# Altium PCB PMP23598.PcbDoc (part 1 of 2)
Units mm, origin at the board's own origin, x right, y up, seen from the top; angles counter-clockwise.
Board outline 80 x 60 mm, 4 copper layers (Top Layer, Layer 1, Layer 2, Bottom Layer), stack 1.856 mm thick; 92 components, 46 nets, 417 pads, 121 vias.
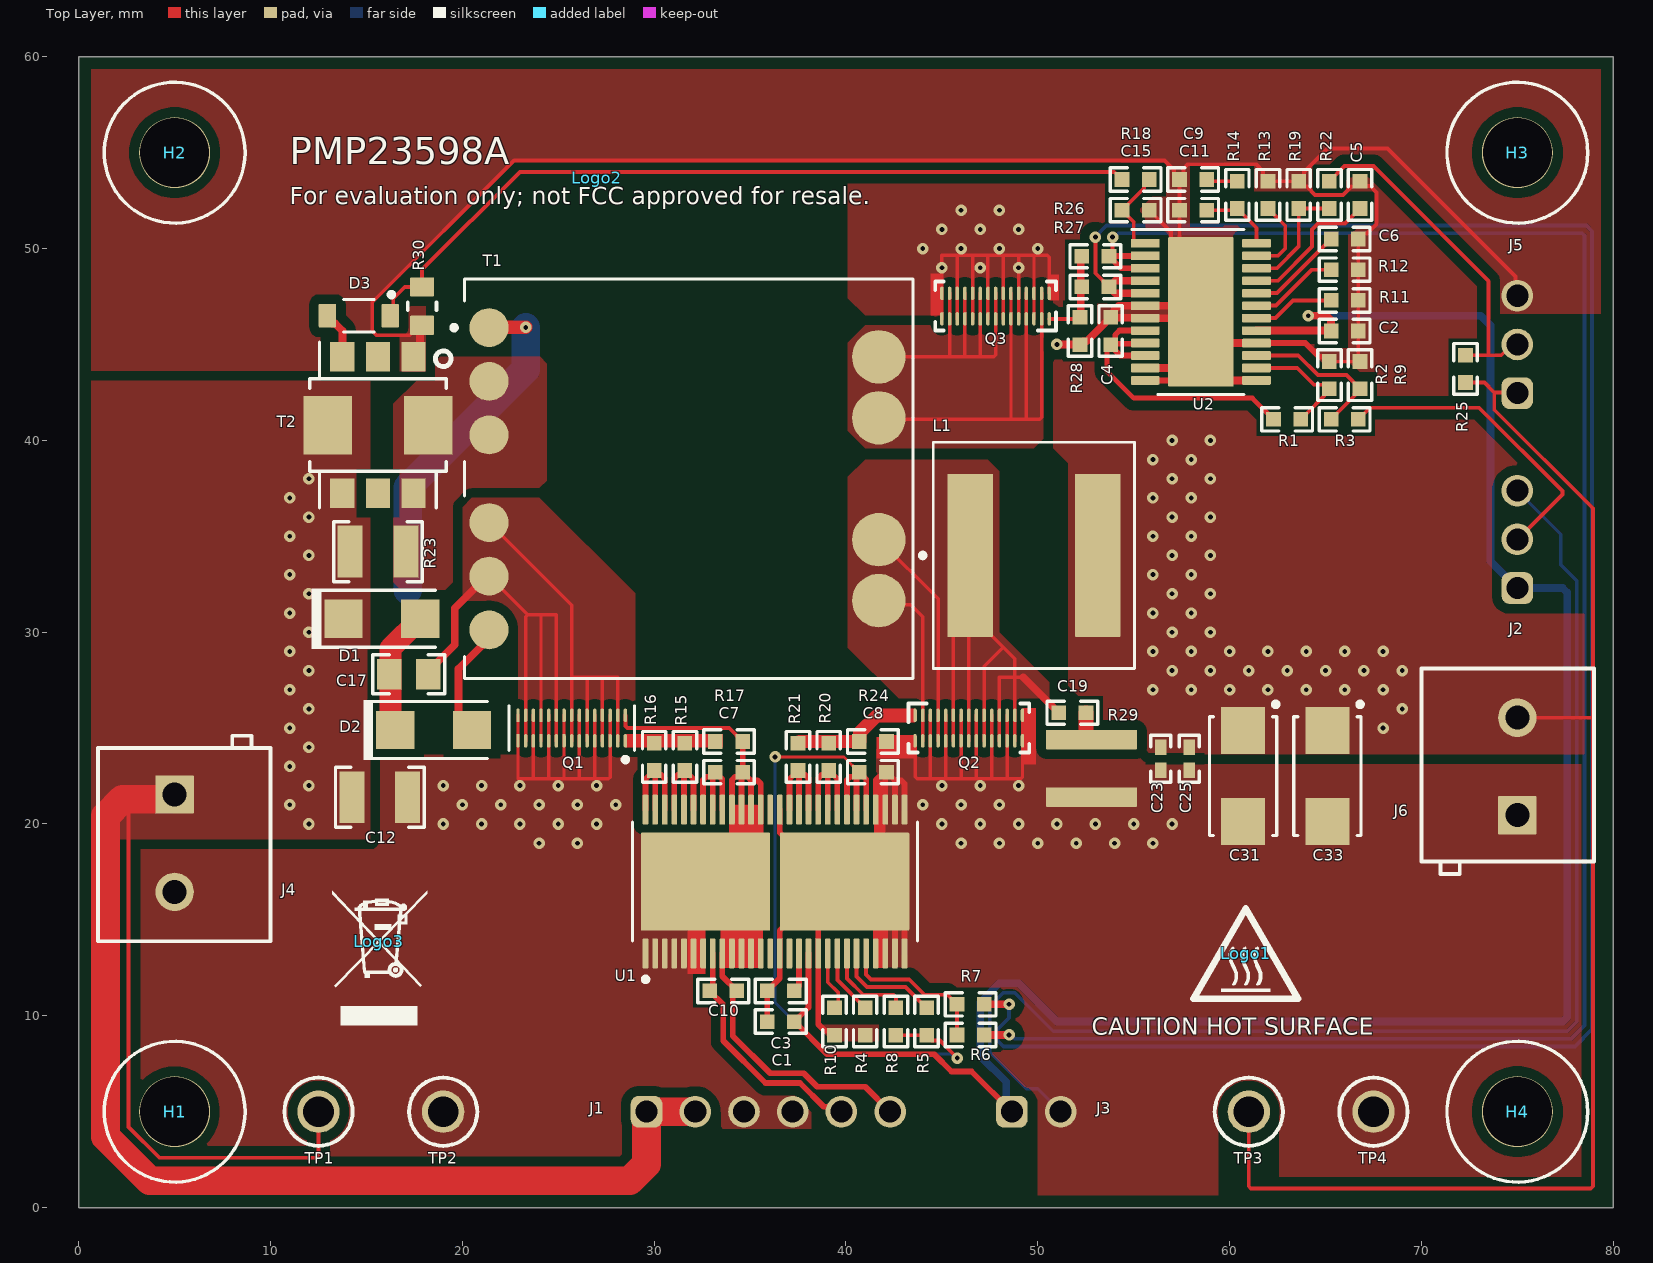
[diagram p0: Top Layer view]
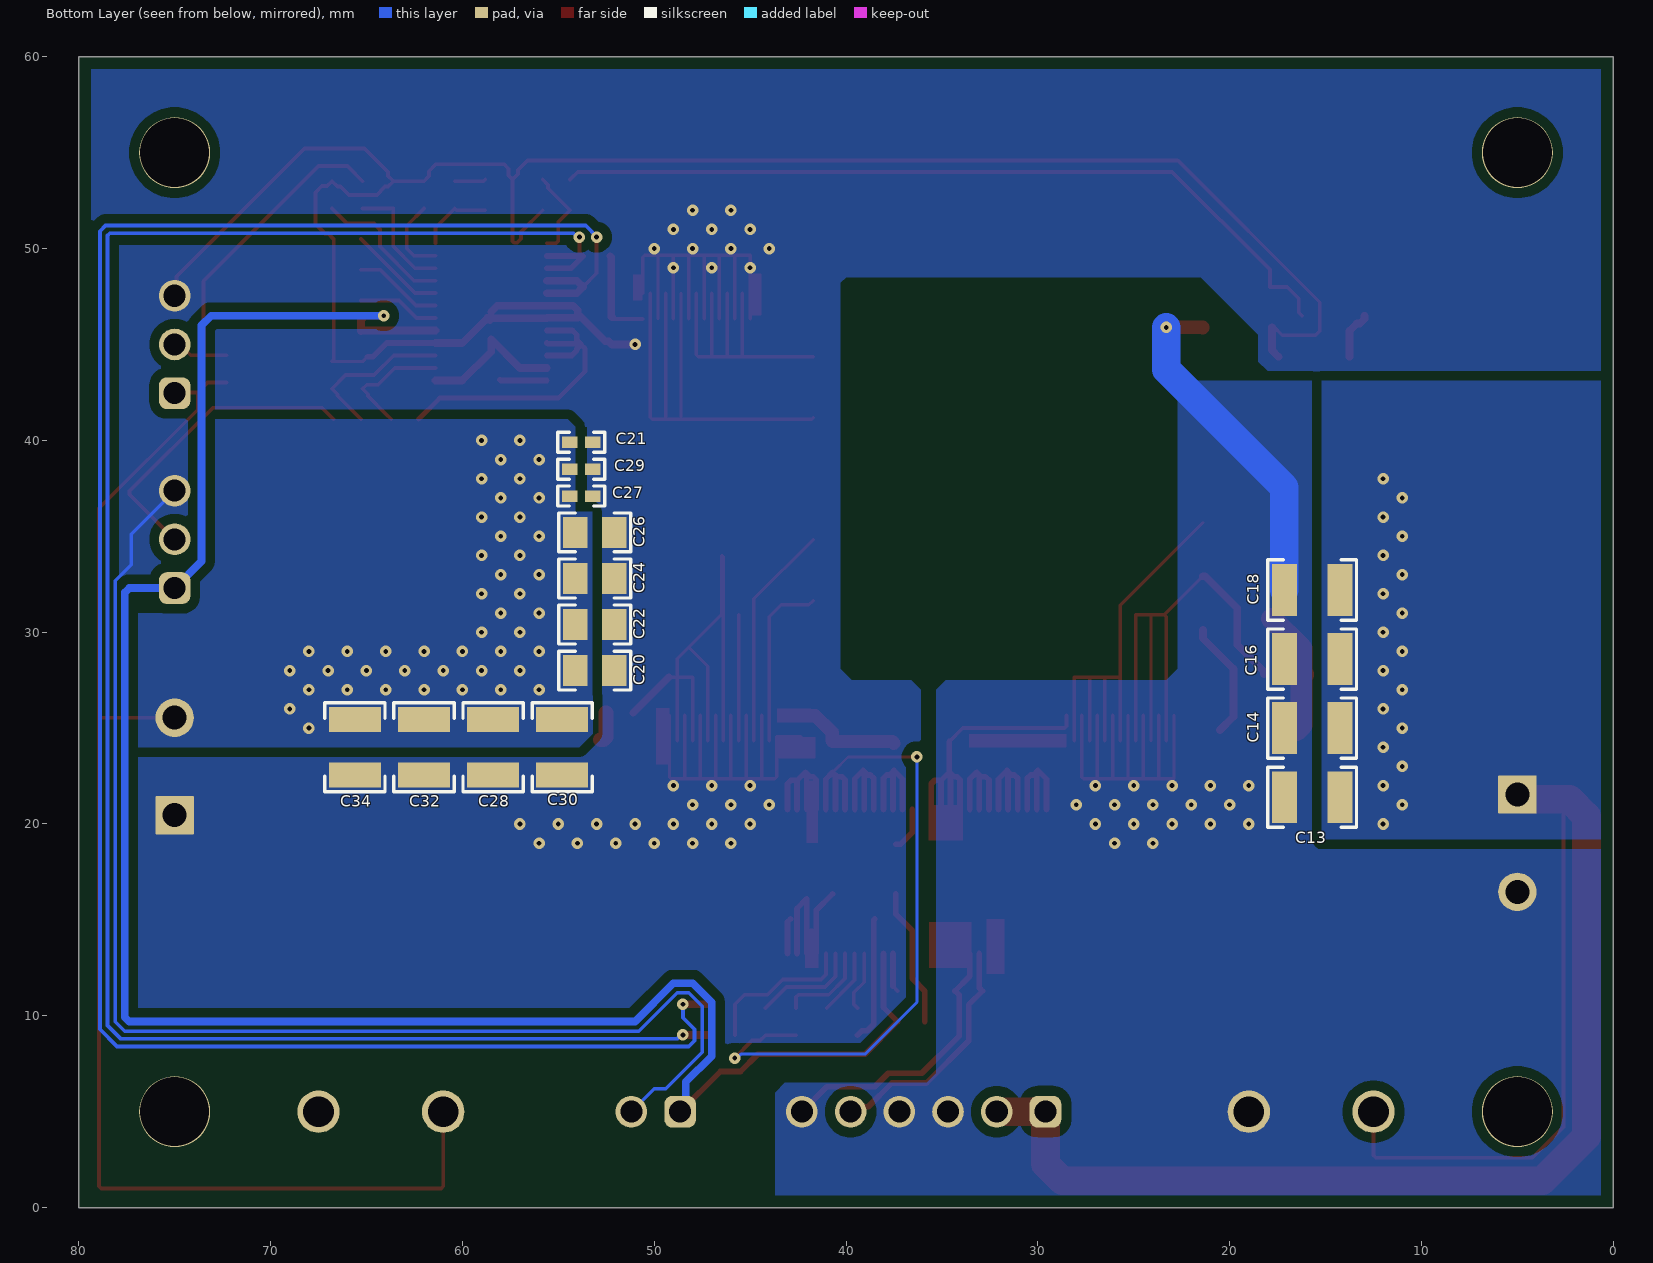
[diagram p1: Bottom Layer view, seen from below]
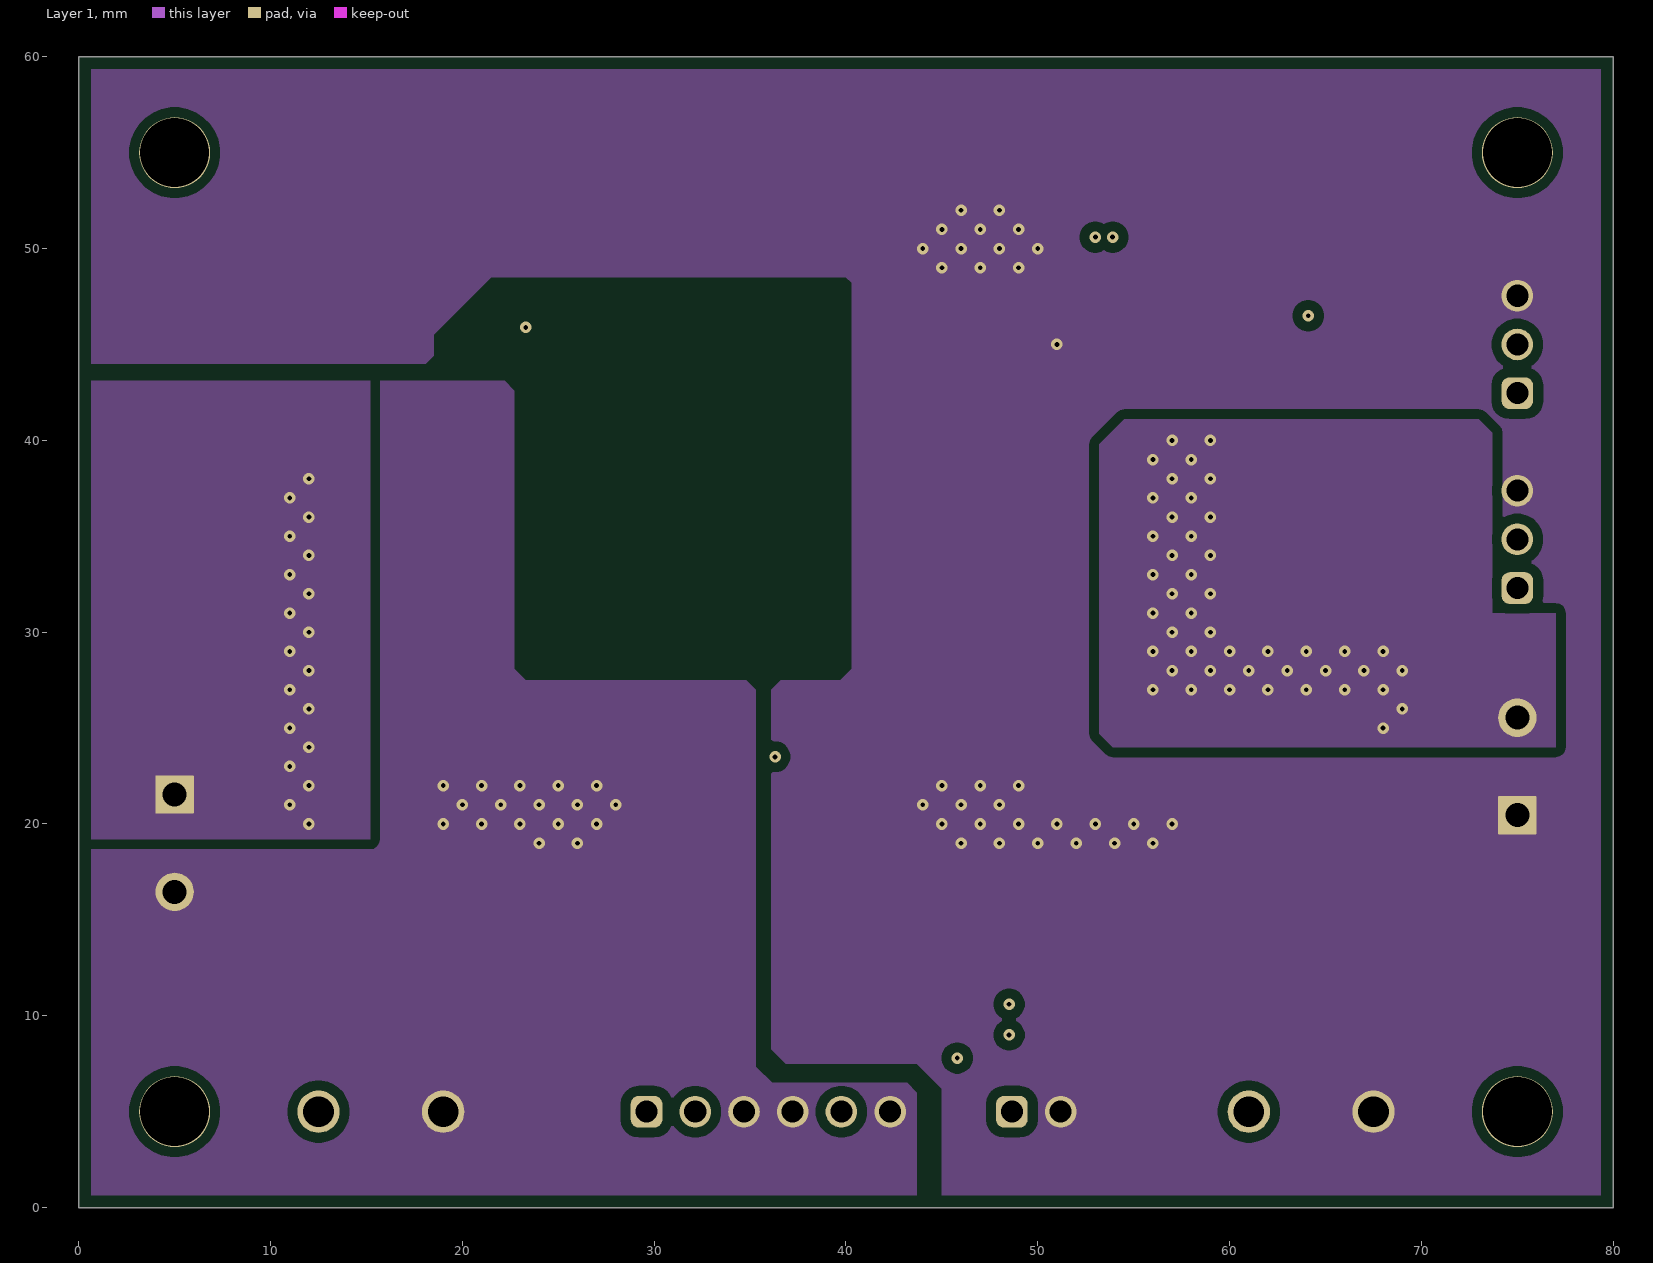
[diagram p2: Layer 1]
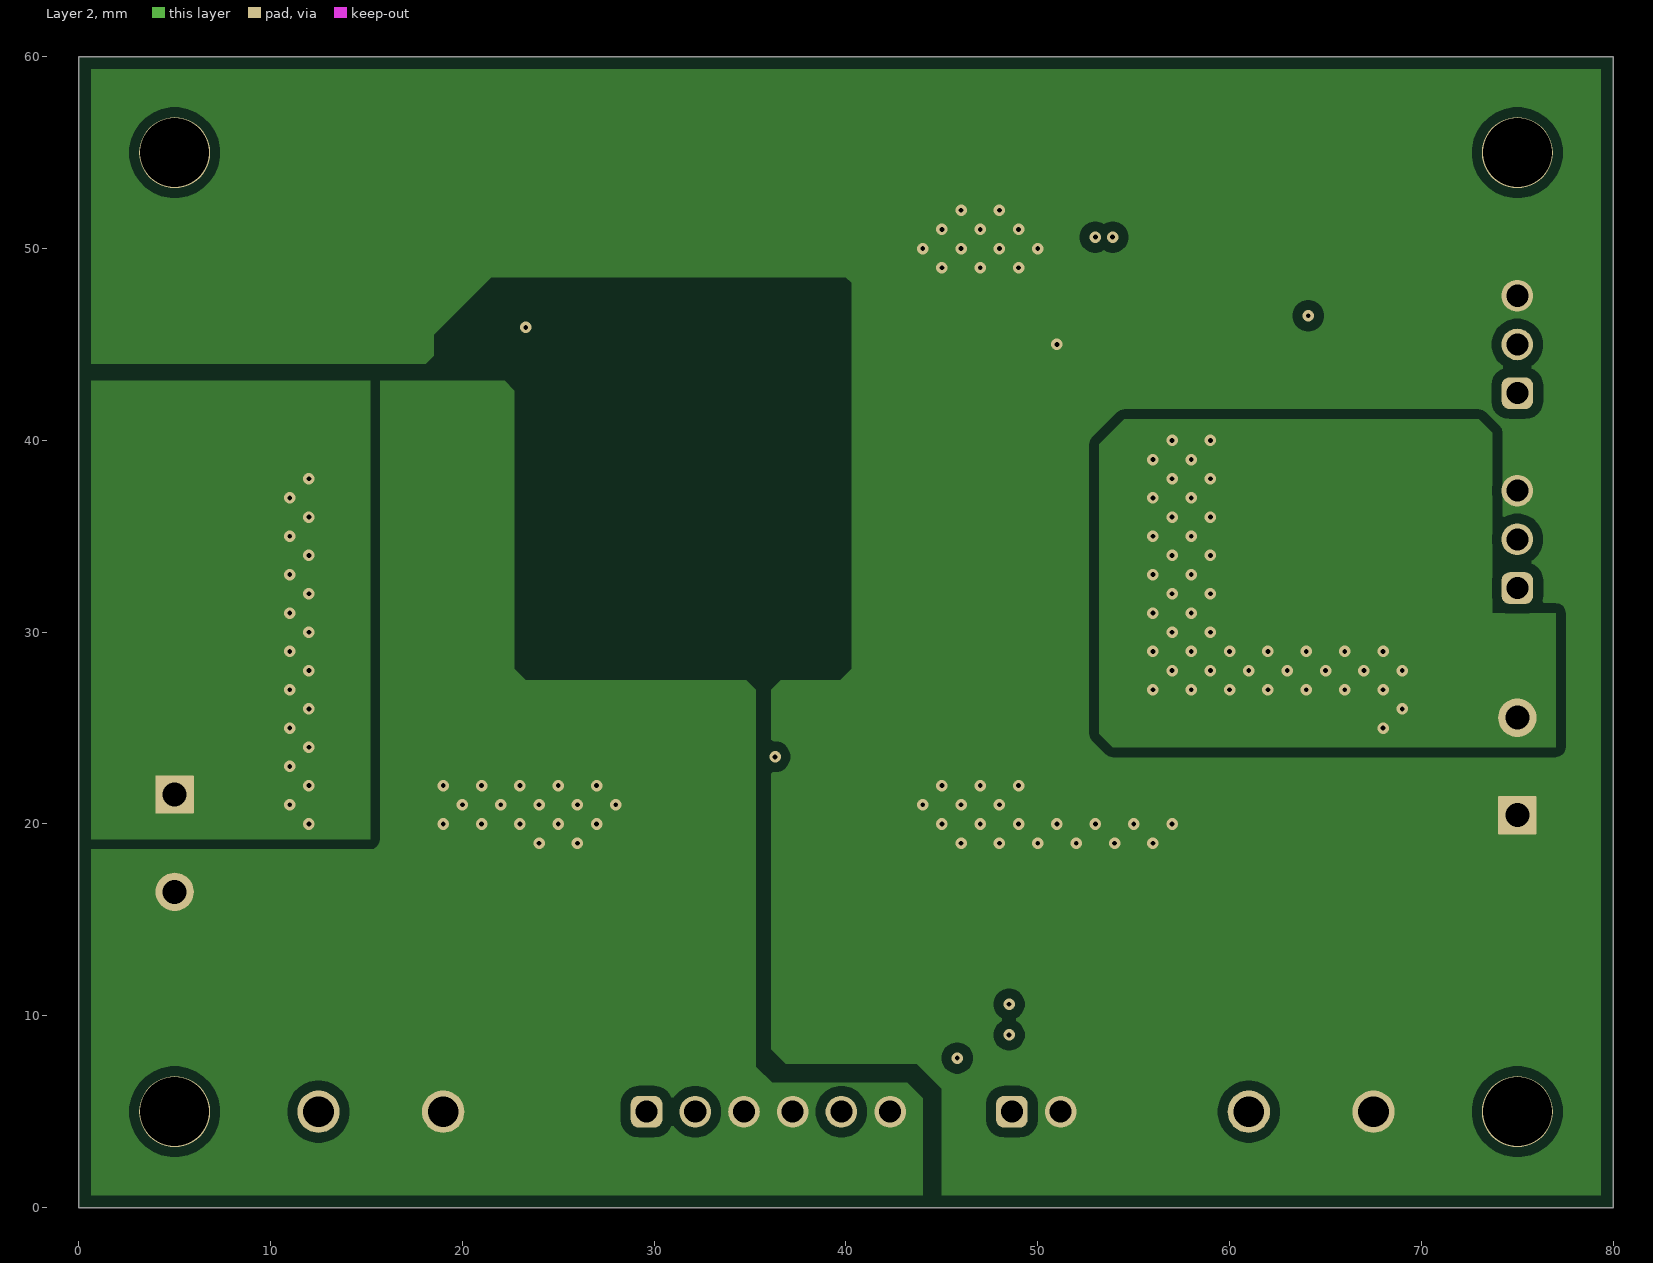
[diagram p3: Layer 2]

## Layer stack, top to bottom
Top Solder: solder mask 0.0102, Solder Resist, Dk 3.5
Top Layer: signal copper 0.07
Dielectric 1: prepreg 0.0711, PP-006, Dk 4.1
Layer 1: signal copper 0.035
Dielectric1: core 1.5037, FR-4 High Tg, Dk 4.8
Layer 2: signal copper 0.035
Dielectric 2: prepreg 0.0711, PP-006, Dk 4.1
Bottom Layer: signal copper 0.07
Bottom Solder: solder mask 0.0102, Solder Resist, Dk 3.5

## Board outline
0,0 0,60 80,60 80,0

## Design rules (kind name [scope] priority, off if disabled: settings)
AcuteAngle [All] p1: minimum=4.50000000000000E+0001 checktracksonly=FALSE
AssemblyTestPointUsage [All] p1: valid=2
BoardOutlineClearance BoardOutlineClearance_MountingHoles [OnCopper and InComponentClass('Mounting Holes')] p1: gap=0.635 ignorepadtopadclearanceinfootprint=FALSE
BoardOutlineClearance BoardOutlineClearance_Poly [OnCopper and InPoly] p2: gap=0.635 ignorepadtopadclearanceinfootprint=FALSE
BoardOutlineClearance [OnCopper and Not InComponentClass('Logo') and not InComponentClass('FiducialMark') and not InRegion(1000,500,4000,800)] p3: gap=0.635 ignorepadtopadclearanceinfootprint=FALSE
Clearance Clearance_2 [InNetClass('HV') vs Not InNetClass('HV')] p1: gap=1.524 ignorepadtopadclearanceinfootprint=FALSE
Clearance Clearance_1 [InNetClass('MV') vs Not InNetClass('MV')] p2: gap=0.762 ignorepadtopadclearanceinfootprint=FALSE
Clearance Clearance_Keepouts [((IsTrack Or IsArc) And Not InPoly) And IsFree and IsKeepOut vs ((IsTrack Or IsArc) And Not InPoly) And IsFree and IsKeepOut] p3: gap=0 ignorepadtopadclearanceinfootprint=FALSE
Clearance Clearance_BoardEdge_MountingHoles [OnCopper and InComponentClass('Mounting Holes') vs IsKeepOut] p4: gap=1.016 ignorepadtopadclearanceinfootprint=FALSE except(0: Arc-Hole Track-Hole SMDPad-Hole THPad-Hole Via-Hole Fill-Hole Poly-Hole Region-Hole Text-Hole)
Clearance Clearance_BoardEdge_Poly [OnCopper and InPoly vs IsKeepOut] p5: gap=1.27 ignorepadtopadclearanceinfootprint=FALSE except(0: Arc-Hole Track-Hole SMDPad-Hole THPad-Hole Via-Hole Fill-Hole Poly-Hole Region-Hole Text-Hole)
Clearance Clearance_BoardEdge [OnCopper and Not InComponentClass('Logo') and not InComponentClass('FiducialMark') and not InRegion(1000,500,4000,800) and Not IsKeepout vs IsKeepOut] p6: gap=1.27 ignorepadtopadclearanceinfootprint=FALSE
Clearance Clearance_Poly [InPolygon] p7: gap=0.508 ignorepadtopadclearanceinfootprint=FALSE except(0: Arc-Hole Track-Hole SMDPad-Hole THPad-Hole Via-Hole Fill-Hole Poly-Hole Region-Hole Text-Hole)
Clearance [All] p8: gap=0.152 ignorepadtopadclearanceinfootprint=FALSE
ComponentClearance ComponentClearance_MountingHoles_FiducialMarks [InComponentClass('Mounting Holes') vs InComponentClass('FiducialMark')] p1: gap=0.508 collisioncheckmode=3 verticalgap=0.254 showdistances=FALSE
ComponentClearance ComponentClearance_Shunt [InComponentClass('Header') vs InComponentClass('Shunt')] p2: gap=0 collisioncheckmode=3 verticalgap=0 showdistances=FALSE
ComponentClearance ComponentClearance_Logo [InComponentClass('Logo')] p3: gap=0.127 collisioncheckmode=3 verticalgap=0.254 showdistances=FALSE
ComponentClearance ComponentClearance_ScrewToNut [(HasFootprint('NY PMS 440 0025 PH')) vs (HasFootprint('Keystone_1902C'))] p4: gap=0.508 collisioncheckmode=3 verticalgap=2540 showdistances=FALSE
ComponentClearance ComponentClearance_MountingHoles [InComponentClass('Mounting Holes')] p5: gap=0.508 collisioncheckmode=3 verticalgap=0.254 showdistances=FALSE
ComponentClearance ComponentClearance_SmallPassives [HasFootprint('0201*') or HasFootprint('0402*') or HasFootprint('0508') or HasFootprint('0603*') or HasFootprint('0612') or HasFootprint('0805*') or HasFootprint('0815*') or HasFootprint('0830*') or HasFootprint('1206*') or HasFootprint('1210*') or HasFootprint('1808*') or HasFootprint('1812*') or HasFootprint('1825*') or HasFootprint('2010*') or HasFootprint('2220*') or HasFootprint('2225*') or HasFootprint('2512*') or HasFootprint('2728*') or HasFootprint('3518*') vs HasFootprint('0201*') or HasFootprint('0402*') or HasFootprint('0508') or HasFootprint('0603*') or HasFootprint('0612') or HasFootprint('0805*') or HasFootprint('0815*') or HasFootprint('0830*') or HasFootprint('1206*') or HasFootprint('1210*') or HasFootprint('1808*') or HasFootprint('1812*') or HasFootprint('1825*') or HasFootprint('2010*') or HasFootprint('2220*') or HasFootprint('2225*') or HasFootprint('2512*') or HasFootprint('2728*') or HasFootprint('3518*')] p6: gap=0.508 collisioncheckmode=3 verticalgap=0.508 showdistances=FALSE
ComponentClearance ComponentClearance_THtoSMT [IsThruComponent vs IsSMTComponent] p7: gap=0.254 collisioncheckmode=3 verticalgap=0.254 showdistances=FALSE
ComponentClearance ComponentClearance_THtoTH [IsThruComponent vs IsThruComponent] p8: gap=0.254 collisioncheckmode=3 verticalgap=0.254 showdistances=FALSE
ComponentClearance [All] p9: gap=0.254 collisioncheckmode=3 verticalgap=0.254 showdistances=FALSE
DiffPairsRouting [All] p1: maxlimit=2.54 minlimit=0.254 mostfreqgap=0.254 toplayer_minwidth=0.381 toplayer_maxwidth=0.381 toplayer_prefwidth=0.381 midlayer1_minwidth=0.381 midlayer1_maxwidth=0.381 midlayer1_prefwidth=0.381 midlayer2_minwidth=0.381 midlayer2_maxwidth=0.381 midlayer2_prefwidth=0.381 bottomlayer_minwidth=0.381 bottomlayer_maxwidth=0.381 bottomlayer_prefwidth=0.381 maxuncoupledlength=25.4
FabricationTestPointUsage TestPointUsage [All] p1: valid=2 allowmultiple=FALSE
FabricationTestpoint Testpoint [All] p1: side=3 testpointundercomponent=TRUE minsize=1.016 maxsize=2.54 preferedsize=1.524 minholesize=0 maxholesize=1.016 preferedholesize=0.813 testpointgrid=0.025 allowsidetop=TRUE allowsidebottom=TRUE usegrid=TRUE gridtolerance=0
FanoutControl Fanout_LCC [IsLCC] p1: bgadir=Out bgaviamode=Centered fanoutstyle=Auto fanoutdirection=Alternating viagrid=0.025 // Fanout_LCC (Default Rule)
FanoutControl Fanout_BGA [IsBGA] p2: bgadir=Out bgaviamode=Centered fanoutstyle=Auto fanoutdirection=Alternating viagrid=0.025 // Fanout_BGA (Default Rule)
FanoutControl Fanout_Default [All] p4: bgadir=Out bgaviamode=Centered fanoutstyle=Auto fanoutdirection=Alternating viagrid=0.025 // Fanout_Default (Default Rule)
FanoutControl Fanout_Small [(CompPinCount < 5)] p5: bgadir=Out bgaviamode=Centered fanoutstyle=Auto fanoutdirection=OutThenIn viagrid=0.025 // Fanout_Small (Default Rule)
Height [All] p1: minheight=0 maxheight=76.2 prefheight=12.7
HoleSize [All] p1: absolutevalues=TRUE maxlimit=6.375 minlimit=0.2 maxpercent=80.000 minpercent=20.000
MinimumAnnularRing MinimumAnnularRing_ThermalPadVias [IsVia and InAnyComponent] p1: minimumring=0.15
MinimumAnnularRing [All] p2: minimumring=0.15
MinimumSolderMaskSliver MinimumSolderMaskSliver_Logo [InComponentClass('Logo') vs InComponentClass('Logo')] p1: minsoldermaskwidth=0.018
MinimumSolderMaskSliver [All] p2: minsoldermaskwidth=0.1
PlaneConnect [All] p1: planeconnectstyle=Direct reliefexpansion=0.254 reliefentries=4 reliefconductorwidth=0.254 reliefairgap=0.254
PolygonConnect PolygonConnect_15 [All vs IsNamedPolygon('C109_2') Or  IsNamedPolygon('C107_2') Or  IsNamedPolygon('HV') Or  IsNamedPolygon('Q203_5') Or  IsNamedPolygon('C107_2') Or  IsNamedPolygon('HS') Or  IsNamedPolygon('Q201_5') Or  IsNamedPolygon('Q203_5') Or  IsNamedPolygon('C106_2') Or  IsNamedPolygon('C108_2') Or  IsNamedPolygon('Vout') Or  IsNamedPolygon('Q203_5') Or  IsNamedPolygon('C108_2') Or  IsNamedPolygon('C113_2') Or  IsNamedPolygon('Q203_5') Or  IsNamedPolygon('Q201_5') Or  IsNamedPolygon('C107_2') Or  IsNamedPolygon('C102_1') Or  IsNamedPolygon('SGND') Or  IsNamedPolygon('GND') Or  IsNamedPolygon('SGND') Or  IsNamedPolygon('GND') Or  IsNamedPolygon('IN+') Or  IsNamedPolygon('IN+') Or  IsNamedPolygon('Q201_5') Or  IsNamedPolygon('Q201_5') Or  IsNamedPolygon('SGND') Or  IsNamedPolygon('SGND') Or  IsNamedPolygon('Vout') Or  IsNamedPolygon('Vout') Or  IsNamedPolygon('IN+') Or  IsNamedPolygon('GND') Or  IsNamedPolygon('IN+') Or  IsNamedPolygon('GND')] p1: connectstyle=Direct reliefconductorwidth=0.254 reliefentries=4 polygonreliefangle="90 Angle" airgapwidth=0.254
PolygonConnect PolygonConnect_14 [All vs IsNamedPolygon('C106_2') Or  IsNamedPolygon('C107_2') Or  IsNamedPolygon('C107_2') Or  IsNamedPolygon('C107_2') Or  IsNamedPolygon('C102_1') Or  IsNamedPolygon('Q203_5') Or  IsNamedPolygon('Vout') Or  IsNamedPolygon('Q203_5') Or  IsNamedPolygon('Q203_5') Or  IsNamedPolygon('Q201_5') Or  IsNamedPolygon('C108_2') Or  IsNamedPolygon('Q203_5') Or  IsNamedPolygon('HS') Or  IsNamedPolygon('HV') Or  IsNamedPolygon('C108_2') Or  IsNamedPolygon('Q201_5') Or  IsNamedPolygon('C109_2') Or  IsNamedPolygon('Q201_5') Or  IsNamedPolygon('Q201_5') Or  IsNamedPolygon('C113_2')] p2: connectstyle=Direct reliefconductorwidth=0.254 reliefentries=4 polygonreliefangle="90 Angle" airgapwidth=0.254
PolygonConnect PolygonConnect_13 [All vs IsNamedPolygon('C102_1') Or  IsNamedPolygon('HV') Or  IsNamedPolygon('C107_2') Or  IsNamedPolygon('C109_2') Or  IsNamedPolygon('C107_2') Or  IsNamedPolygon('C108_2') Or  IsNamedPolygon('C106_2') Or  IsNamedPolygon('C108_2') Or  IsNamedPolygon('C113_2') Or  IsNamedPolygon('C107_2')] p3: connectstyle=Direct reliefconductorwidth=0.254 reliefentries=4 polygonreliefangle="90 Angle" airgapwidth=0.254
PolygonConnect PolygonConnect_12 [All vs IsNamedPolygon('C107_2') Or  IsNamedPolygon('C113_2') Or  IsNamedPolygon('C106_2') Or  IsNamedPolygon('C107_2') Or  IsNamedPolygon('C107_2') Or  IsNamedPolygon('C102_1')] p4: connectstyle=Direct reliefconductorwidth=0.254 reliefentries=4 polygonreliefangle="90 Angle" airgapwidth=0.254
PolygonConnect PolygonConnect_11 [All vs IsNamedPolygon('C106_2') Or  IsNamedPolygon('C102_1') Or  IsNamedPolygon('C107_2') Or  IsNamedPolygon('C107_2') Or  IsNamedPolygon('C107_2')] p5: connectstyle=Direct reliefconductorwidth=0.254 reliefentries=4 polygonreliefangle="90 Angle" airgapwidth=0.254
PolygonConnect PolygonConnect_10 [All vs IsNamedPolygon('C106_2')] p6: connectstyle=Direct reliefconductorwidth=0.254 reliefentries=4 polygonreliefangle="90 Angle" airgapwidth=0.254
PolygonConnect PolygonConnect_9 [All vs IsNamedPolygon('C11_1') Or  IsNamedPolygon('Vin') Or  IsNamedPolygon('Vin') Or  IsNamedPolygon('5V') Or  IsNamedPolygon('D6_2') Or  IsNamedPolygon('Q3_3') Or  IsNamedPolygon('GND2') Or  IsNamedPolygon('GND2') Or  IsNamedPolygon('GND') Or  IsNamedPolygon('Q3_4') Or  IsNamedPolygon('12V5') Or  IsNamedPolygon('GND') Or  IsNamedPolygon('12V5') Or  IsNamedPolygon('D3_1')] p7: connectstyle=Direct reliefconductorwidth=0.254 reliefentries=4 polygonreliefangle="90 Angle" airgapwidth=0.254
PolygonConnect PolygonConnect_8 [All vs IsNamedPolygon('C11_1') Or  IsNamedPolygon('Vin') Or  IsNamedPolygon('12V5') Or  IsNamedPolygon('Q3_3') Or  IsNamedPolygon('GND2') Or  IsNamedPolygon('GND2') Or  IsNamedPolygon('5V') Or  IsNamedPolygon('Q3_4') Or  IsNamedPolygon('12V5')] p8: connectstyle=Direct reliefconductorwidth=0.254 reliefentries=4 polygonreliefangle="90 Angle" airgapwidth=0.254
PolygonConnect PolygonConnect_7 [All vs IsNamedPolygon('GND2') Or  IsNamedPolygon('GND2') Or  IsNamedPolygon('5V') Or  IsNamedPolygon('12V5') Or  IsNamedPolygon('12V5') Or  IsNamedPolygon('C11_1')] p9: connectstyle=Direct reliefconductorwidth=0.254 reliefentries=4 polygonreliefangle="90 Angle" airgapwidth=0.254
PolygonConnect PolygonConnect_6 [All vs IsNamedPolygon('GND2') Or  IsNamedPolygon('SGND') Or  IsNamedPolygon('GND1') Or  IsNamedPolygon('C901_1') Or  IsNamedPolygon('SGND') Or  IsNamedPolygon('GND2') Or  IsNamedPolygon('GND1')] p10: connectstyle=Direct reliefconductorwidth=0.254 reliefentries=4 polygonreliefangle="90 Angle" airgapwidth=0.254
PolygonConnect PolygonConnect_5 [All vs IsNamedPolygon('GND1') Or  IsNamedPolygon('GND1')] p11: connectstyle=Direct reliefconductorwidth=0.254 reliefentries=4 polygonreliefangle="90 Angle" airgapwidth=0.254
PolygonConnect PolygonConnect_4 [All vs IsNamedPolygon('C21_1') Or  IsNamedPolygon('C5_1') Or  IsNamedPolygon('C12_2') Or  IsNamedPolygon('C2_2') Or  IsNamedPolygon('C13_1') Or  IsNamedPolygon('C28_1') Or  IsNamedPolygon('C6_1') Or  IsNamedPolygon('GND') Or  IsNamedPolygon('GND2') Or  IsNamedPolygon('C14_1') Or  IsNamedPolygon('C13_1') Or  IsNamedPolygon('Q1_3') Or  IsNamedPolygon('C14_1') Or  IsNamedPolygon('C5_1') Or  IsNamedPolygon('GND2') Or  IsNamedPolygon('C28_1') Or  IsNamedPolygon('D5_2') Or  IsNamedPolygon('D6_2') Or  IsNamedPolygon('D2_1') Or  IsNamedPolygon('C12_2') Or  IsNamedPolygon('D2_1') Or  IsNamedPolygon('C4_1') Or  IsNamedPolygon('C4_1') Or  IsNamedPolygon('C2_2') Or  IsNamedPolygon('GND') Or  IsNamedPolygon('C33_1') Or  IsNamedPolygon('C9_1')] p12: connectstyle=Direct reliefconductorwidth=0.254 reliefentries=4 polygonreliefangle="90 Angle" airgapwidth=0.254
PolygonConnect PolygonConnect_3 [All vs IsNamedPolygon('C28_1') Or  IsNamedPolygon('C12_2') Or  IsNamedPolygon('C28_1') Or  IsNamedPolygon('C9_1') Or  IsNamedPolygon('D5_2') Or  IsNamedPolygon('C12_2') Or  IsNamedPolygon('C2_2') Or  IsNamedPolygon('C14_1') Or  IsNamedPolygon('C4_1') Or  IsNamedPolygon('C14_1') Or  IsNamedPolygon('D6_2') Or  IsNamedPolygon('GND2') Or  IsNamedPolygon('Q1_3') Or  IsNamedPolygon('C5_1') Or  IsNamedPolygon('D2_1') Or  IsNamedPolygon('C4_1') Or  IsNamedPolygon('C13_1') Or  IsNamedPolygon('C5_1') Or  IsNamedPolygon('C13_1') Or  IsNamedPolygon('C33_1') Or  IsNamedPolygon('D2_1') Or  IsNamedPolygon('GND') Or  IsNamedPolygon('GND') Or  IsNamedPolygon('GND2') Or  IsNamedPolygon('C2_2') Or  IsNamedPolygon('C6_1') Or  IsNamedPolygon('C21_1')] p13: connectstyle=Direct reliefconductorwidth=0.254 reliefentries=4 polygonreliefangle="90 Angle" airgapwidth=0.254
PolygonConnect PolygonConnect_2 [All vs IsNamedPolygon('C21_1') Or  IsNamedPolygon('C4_1') Or  IsNamedPolygon('D5_2') Or  IsNamedPolygon('C5_1') Or  IsNamedPolygon('C14_1') Or  IsNamedPolygon('C13_1') Or  IsNamedPolygon('C4_1') Or  IsNamedPolygon('C33_1') Or  IsNamedPolygon('C12_2') Or  IsNamedPolygon('D2_1') Or  IsNamedPolygon('C2_2') Or  IsNamedPolygon('C28_1') Or  IsNamedPolygon('C12_2') Or  IsNamedPolygon('D2_1') Or  IsNamedPolygon('C5_1') Or  IsNamedPolygon('Q1_3') Or  IsNamedPolygon('GND') Or  IsNamedPolygon('D6_2') Or  IsNamedPolygon('C6_1') Or  IsNamedPolygon('C2_2') Or  IsNamedPolygon('C14_1') Or  IsNamedPolygon('C28_1') Or  IsNamedPolygon('C13_1') Or  IsNamedPolygon('C9_1') Or  IsNamedPolygon('GND')] p14: connectstyle=Direct reliefconductorwidth=0.254 reliefentries=4 polygonreliefangle="90 Angle" airgapwidth=0.254
PolygonConnect PolygonConnect_1 [All vs IsNamedPolygon('C28_1') Or  IsNamedPolygon('D5_2') Or  IsNamedPolygon('C5_1') Or  IsNamedPolygon('C5_1') Or  IsNamedPolygon('D2_1') Or  IsNamedPolygon('C21_1') Or  IsNamedPolygon('C9_1') Or  IsNamedPolygon('C4_1') Or  IsNamedPolygon('C14_1') Or  IsNamedPolygon('C28_1') Or  IsNamedPolygon('C6_1') Or  IsNamedPolygon('C12_2') Or  IsNamedPolygon('C33_1') Or  IsNamedPolygon('C4_1') Or  IsNamedPolygon('C13_1') Or  IsNamedPolygon('C12_2') Or  IsNamedPolygon('D6_2') Or  IsNamedPolygon('C2_2') Or  IsNamedPolygon('C14_1') Or  IsNamedPolygon('D2_1') Or  IsNamedPolygon('C2_2') Or  IsNamedPolygon('C13_1')] p15: connectstyle=Direct reliefconductorwidth=0.254 reliefentries=4 polygonreliefangle="90 Angle" airgapwidth=0.254
PolygonConnect [All] p16: connectstyle=Direct reliefconductorwidth=0.254 reliefentries=4 polygonreliefangle="90 Angle" airgapwidth=0.254
RoutingVias ThermalPadVias [IsVia and InAnyComponent] p1: holewidth=0.2 width=0.5 viastyle="Through Hole" minholewidth=0.2 minwidth=0.5 maxholewidth=0.33 maxwidth=0.6
RoutingVias [All] p2: holewidth=0.406 width=0.864 viastyle="Through Hole" minholewidth=0.15 minwidth=0.25 maxholewidth=1.016 maxwidth=1.651
SilkToBoardRegionClearance [Not ((IsComment or IsDesignator) And (Hide <> 'False')) and not InRegion(1000,500,4000,800)] p1:
SilkToSilkClearance SilkToSilkClearance_Pb-FreeLogo [(HasFootprint('Pb-Free_Overlay_Medium') OR HasFootprint('Pb-Free_Overlay_Small')) vs (HasFootprint('Pb-Free_Overlay_Medium') OR HasFootprint('Pb-Free_Overlay_Small'))] p1: silktosilkclearance=0
SilkToSilkClearance [All] p2: silktosilkclearance=0.102
SilkToSolderMaskClearance SilkToComponentPadClearance [IsPad and InAnycomponent] p1: minsilkscreentomaskgap=0.127 clearancetoexposedcopper=TRUE
SilkToSolderMaskClearance "Silk to Solder Mask Opening" [All] p2: minsilkscreentomaskgap=0.102 clearancetoexposedcopper=FALSE
SolderMaskExpansion [All] p1: expansion=0.05 istentingtop=FALSE
SupplyNets "Schematic Supply Nets_6" [InNet('+12Vs')] p1: voltage=0.000
SupplyNets "Schematic Supply Nets_5" [InNet('PGND')] p2: voltage=0.000
SupplyNets "Schematic Supply Nets_4" [InNet('SGND')] p3: voltage=0.000
SupplyNets "Schematic Supply Nets_3" [InNet('VIN')] p4: voltage=0.000
SupplyNets "Schematic Supply Nets_2" [InNet('BP5L')] p5: voltage=0.000
SupplyNets "Schematic Supply Nets_1" [InNet('VOUT')] p6: voltage=0.000
SupplyNets "Schematic Supply Nets" [InNet('+12Vp')] p7: voltage=0.000
Width [All] p1: maxlimit=2.54 minlimit=0.152 preferedwidth=0.254 checkconnectedcopper=TRUE
14 further rules are at their usual default settings.

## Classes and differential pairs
component class Header: J1 J2 J3 J5

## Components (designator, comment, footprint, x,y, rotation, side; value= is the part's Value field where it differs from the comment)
C1 "GRM188R71E105KA12D" 0603_HV 36.6,9.7 r180 top value=1uF
C2 "GRM188R71E105KA12D" 0603_HV 66,45.7 r0 top value=1uF
C3 "GRM188R71E105KA12D" 0603_HV 36.6,11.3 r0 top value=1uF
C4 "GRM188R71E105KA12D" 0603_HV 53.8,45.7 r90 top value=1uF
C5 "GRM188R71E102KA01D" 0603_HV 66.8,52.8 r270 top value=1000pF
C6 "GCM188R71C474KA55D" 0603_HV 66,50.5 r0 top value=0.47uF
C7 "GRM188Z71C225KE43" 0603_HV 33.9,22.7 r180 top value=2.2uF
C8 "GRM188Z71C225KE43" 0603_HV 41.4,22.7 r180 top value=2.2uF
C9 "GRM188R71H332KA01D" 0603_HV 58.1,53.6 r180 top value=3300pF
C10 "GRM188R71E105KA12D" 0603_HV 33.6,11.3 r0 top value=1uF
C11 "GCM1885C1H680JA16D" 0603_HV 58.1,52 r0 top value=68pF
C12 "GCM32EL8EH106KA07L" 1210_270 15.7,21.4 r0 top value=10uF
C13 "GCM32EL8EH106KA07L" 1210_270 15.7,21.4 r0 bottom value=10uF
C14 "GCM32EL8EH106KA07L" 1210_270 15.7,25 r0 bottom value=10uF
C15 "GCM1885C2A100JA16D" 0603_HV 55.1,52 r0 top value=10pF
C16 "GCM32EL8EH106KA07L" 1210_270 15.7,28.6 r0 bottom value=10uF
C17 "GRM21BR71H104KA01L" 0805_HV 17.2,27.8 r0 top value=0.1uF
C18 "GCM32EL8EH106KA07L" 1210_270 15.7,32.2 r0 bottom value=10uF
C19 "GRM188R71H222KA01D" 0603_HV 51.8,25.8 r0 top value=2200pF
C20 "GRM216R71A224KC01D" 0805_HV 53.1,28 r0 bottom value=0.22uF
C21 "GRM155R71H221KA01D" 0402 53.8,39.9 r180 bottom value=220pF
C22 "GRM216R71A224KC01D" 0805_HV 53.1,30.4 r0 bottom value=0.22uF
C23 "GRM155R71H221KA01D" 0402 56.4,23.4 r270 top value=220pF
C24 "GRM216R71A224KC01D" 0805_HV 53.1,32.8 r0 bottom value=0.22uF
C25 "GRM155R71H221KA01D" 0402 57.9,23.4 r270 top value=220pF
C26 "GRM216R71A224KC01D" 0805_HV 53.1,35.2 r0 bottom value=0.22uF
C27 "GRM155R71H221KA01D" 0402 53.8,37.1 r180 bottom value=220pF
C28 "C1210C475K8RACTU" 1210 58.4,24 r270 bottom value=4.7uF
C29 "GRM155R71H221KA01D" 0402 53.8,38.5 r180 bottom value=220pF
C30 "C1210C475K8RACTU" 1210 54.8,24 r270 bottom value=4.7uF
C31 "T495U107K010ZTE150" 6032-15 60.7,22.5 r270 top value=100uF
C32 "C1210C475K8RACTU" 1210 62,24 r270 bottom value=4.7uF
C33 "T495U107K010ZTE150" 6032-15 65.1,22.5 r270 top value=100uF
C34 "C1210C475K8RACTU" 1210 65.6,24 r270 bottom value=4.7uF
D1 "SS110-TP" SMA 15.8,30.7 r0 top value=100V
D2 "SS110-TP" SMA 18.5,24.9 r0 top value=100V
D3 "BAT46GWJ" FP-BAT46GWJ_SOD-123-MFG 14.6,46.5 r180 top
H1 "4820" KEYSTONE_4820 5,5 r0 top
H2 "4820" KEYSTONE_4820 5,55 r0 top
H3 "4820" KEYSTONE_4820 75,55 r0 top
H4 "4820" KEYSTONE_4820 75,5 r0 top
J1 "61300611121" WURTH_61300611121 35.95,5 r0 top
J2 "61300311121" WURTH_61300311121 75,34.84 r90 top
J3 "61300211121" WURTH_61300211121 49.92,5 r0 top
J4 "ED120/2DS" On-Shore_ED120_2DS 5,19 r270 top
J5 "61300311121" WURTH_61300311121 75,45 r90 top
J6 "ED120/2DS" On-Shore_ED120_2DS 75,23 r90 top
L1 "XGL1060-222MEC" FP-XGL1060-222MEC_SMD2-MFG 49.8,34 r0 top value=2.2uH
Logo1 "CAUTION HOT SURFACE" IEC_HotSurface_Small 60.841,13.25 r0 top
Logo2 "FCC disclaimer" FCC_disclaimer 27,53.7 r0 top
Logo3 "WEEE logo" WEEE_Minimum 15.65,13.875 r0 top
Q1 "EPC2022" FP-EPC2022_LGA30-MFG 25.7,25 r180 top
Q2 "EPC2024" EPC2023 46.4,25 r90 top value=40V
Q3 "EPC2024" EPC2023 47.8,47 r270 top value=40V
R1 "CRCW060310K0FKEA" 0603_HV 63,41.1 r180 top value=10.0k
R2 "CRCW06033K16FKEA" 0603_HV 65.2,43.4 r90 top value=3.16k
R3 "CRCW060310K0FKEA" 0603_HV 66,41.1 r0 top value=10.0k
R4 "CRCW060359K0FKEA" 0603_HV 41,9.7 r90 top value=59.0k
R5 "CRCW06031R00FKEA" 0603_HV 44.2,9.7 r270 top value=1.00
R6 "CRCW06031R00FKEA" 0603_HV 46.5,9 r0 top value=1.00
R7 "CRCW06031R00FKEA" 0603_HV 46.5,10.6 r0 top value=1.00
R8 "RG1608P-103-B-T5" 0603_HV 42.6,9.7 r90 top value=10.0k
R9 "CRCW060310K0FKEA" 0603_HV 66.8,43.4 r270 top value=10.0k
R10 "CRCW060359K0FKEA" 0603_HV 39.4,9.7 r90 top value=59.0k
R11 "CRCW0603499KFKEA" 0603_HV 66,47.3 r180 top value=499k
R12 "CRCW0603432KFKEA" 0603_HV 66,48.9 r180 top value=432k
R13 "CRCW0603499KFKEA" 0603_HV 62,52.8 r270 top value=499k
R14 "CRCW060317K8FKEA" 0603_HV 60.4,52.8 r90 top value=17.8k
R15 "CRCW06031R80FKEA" 0603_HV 31.6,23.5 r90 top value=1.80
R16 "CRCW06031R80FKEA" 0603_HV 30,23.5 r90 top value=1.80
R17 "CRCW060310K0FKEA" 0603_HV 33.9,24.3 r0 top value=10.0k
R18 "CRCW06031K43FKEA" 0603_HV 55.1,53.6 r180 top value=1.43k
R19 "CRCW06031K43FKEA" 0603_HV 63.6,52.8 r270 top value=1.43k
R20 "CRCW06032R87FKEA" 0603_HV 39.1,23.5 r90 top value=2.87
R21 "CRCW06032R87FKEA" 0603_HV 37.5,23.5 r90 top value=2.87
R22 "CRCW060310K0FKEA" 0603_HV 65.2,52.8 r90 top value=10.0k
R23 "ERJ14RSJR10U" 1210 15.6,34.2 r180 top value=0.1
R24 "CRCW060310K0FKEA" 0603_HV 41.4,24.3 r0 top value=10.0k
R25 "CRCW060310R0FKEA" 0603_HV 72.3,43.73 r270 top value=10.0
R26 "CRCW06032R87FKEA" 0603_HV 53,49.6 r0 top value=2.87
R27 "CRCW06032R87FKEA" 0603_HV 53,48 r0 top value=2.87
R28 "CRCW060310K0FKEA" 0603_HV 52.2,45.7 r90 top value=10.0k
R29 "CRCW121810R0FKEK" 1218 52.8,22.9 r90 top value=10.0
R30 "CRCW08052R21FKEA" 0805_HV1 17.9,47 r90 top value=2.21
T1 "ZG3406-AL" FP-ZG3406-AL_SMT_XFRMR_23MM37_20MM83-MFG 31.8,38 r0 top
T2 "PA1005.050NL" P82xx 15.6,40.8 r270 top
TP1 "5010" Keystone5010 12.5,5 r0 top
TP2 "5011" Keystone5011 19,5 r0 top
TP3 "5010" Keystone5010 61,5 r0 top
TP4 "5011" Keystone5011 67.5,5 r0 top
U1 "TPS7H6005/EM" DCA0056M-MFG 36.3,17 r90 top
U2 "TPS7H5021MPWPTSEP" PWP0024R-MFG 58.5,46.7 r0 top

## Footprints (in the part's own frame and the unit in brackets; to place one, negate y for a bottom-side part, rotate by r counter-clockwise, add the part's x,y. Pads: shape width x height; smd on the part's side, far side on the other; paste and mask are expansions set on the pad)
0402 [mm] "0402 from SM-752 data"
  rect 0.8x0.6 smd: 1(-0.6,0) 2(0.6,0)
  silkscreen extent -1.22,-0.52 1.22,0.52, body extent -0.55,-0.3 0.55,0.3, height 0.6
0603_HV [mil] "Ernesto recommended land pattern.  26 mil between pads."
  rect 30x30 smd: 1(-28,0) 2(28,0)
  silkscreen extent -52,-24 52,24, body extent -34,-19 34,19, height 39
0805_HV [mil] "0805 with 30mil clearance between pads"
  rect 50x63 smd: 1(-40,0) 2(40,0)
  silkscreen extent -74,-40 74,40, body extent -43,-29 43,29, height 57
0805_HV1 [mm] "Custom footprint based on analyzing multiple manufacturer recommendations"
  rrect10% 1x1.25 smd: 1(-1,0) 2(1,0)
  silkscreen extent -0.2,-0.75 0.2,0.75, body extent -1.1,-0.72 1.1,0.73, height 1.45
1210 [mm] "1210 from SM-752 data"
  rect 1.3x2.7 smd: 1(-1.45,0) 2(1.45,0)
  silkscreen extent -2.32,-1.57 2.32,1.57, body extent -1.7,-1.35 1.7,1.35, height 1.35
1210_270 [mm] "1210"
  rect 1.3x2.7 smd: 1(-1.45,0) 2(1.45,0)
  silkscreen extent -2.32,-1.57 2.32,1.57, body extent -1.7,-1.35 1.7,1.35, height 2.7
1218 [mil] "Vishay recommended land pattern for 1218, document number 20008 revision 13-Oct-08"
  rrect10% 40x187 smd: 1(-59,0) 2(59,0)
  body extent -65,-93 65,93, height 24
6032-15 [mm] "Medium density IPC, based on AVX TPS series case W"
  rect 2.45x2.3 smd: 1(-2.375,0) 2(2.375,0)
  silkscreen extent -3.86,-1.75 3.1,1.83, body extent -3.1,-1.7 3.1,1.7, height 1.7
DCA0056M-MFG [mm]
  rrect33% 1.55x0.3 smd paste+0 mask+0: 1(-3.75,6.75) 2(-3.75,6.25) 3(-3.75,5.75) 4(-3.75,5.25) 5(-3.75,4.75) 6(-3.75,4.25) 7(-3.75,3.75) 8(-3.75,3.25) 9(-3.75,2.75) 10(-3.75,2.25) 11(-3.75,1.75) 12(-3.75,1.25) 13(-3.75,0.75) 14(-3.75,0.25) 15(-3.75,-0.25) 16(-3.75,-0.75) 17(-3.75,-1.25) 18(-3.75,-1.75) 19(-3.75,-2.25) 20(-3.75,-2.75) 21(-3.75,-3.25) 22(-3.75,-3.75) 23(-3.75,-4.25) 24(-3.75,-4.75) 25(-3.75,-5.25) 26(-3.75,-5.75) 27(-3.75,-6.25) 28(-3.75,-6.75) 29(3.75,-6.75) 30(3.75,-6.25) 31(3.75,-5.75) 32(3.75,-5.25) 33(3.75,-4.75) 34(3.75,-4.25) 35(3.75,-3.75) 36(3.75,-3.25) 37(3.75,-2.75) 38(3.75,-2.25) 39(3.75,-1.75) 40(3.75,-1.25) 41(3.75,-0.75) 42(3.75,-0.25) 43(3.75,0.25) 44(3.75,0.75) 45(3.75,1.25) 46(3.75,1.75) 47(3.75,2.25) 48(3.75,2.75) 49(3.75,3.25) 50(3.75,3.75) 51(3.75,4.25) 52(3.75,4.75) 53(3.75,5.25) 54(3.75,5.75) 55(3.75,6.25) 56(3.75,6.75)
  rrect2% 5.1x6.75 smd paste-1000 mask-1000: 57(0,3.625) 58(0,-3.625)
  silkscreen extent -5.22,-7.42 3.1,7.42, body extent -4.62,-7.15 4.62,7.15, height 0.25
EPC2023 [mm] "SMD, 30-Leads, Body 6.05x2.3mm, Pitch 0.4mm"
  oval 0.7x0.18 smd paste-0.7 mask-0.01: 1(0.665,2.8) 2(-0.665,2.8) 3(0.665,2.4) 4(-0.665,2.4) 5(0.665,2) 6(-0.665,2) 7(0.665,1.6) 8(-0.665,1.6) 9(0.665,1.2) 10(-0.665,1.2) 11(0.665,0.8) 12(-0.665,0.8) 13(0.665,0.4) 14(-0.665,0.4) 15(0.665,0) 16(-0.665,0) 17(0.665,-0.4) 18(-0.665,-0.4) 19(0.665,-0.8) 20(-0.665,-0.8) 21(0.665,-1.2) 22(-0.665,-1.2) 23(0.665,-1.6) 24(-0.665,-1.6) 25(0.665,-2) 26(-0.665,-2) 27(0.665,-2.4) 28(-0.665,-2.4) 29(0.665,-2.8) 30(-0.665,-2.8)
  rrect67% 0.7x0.18 on Top Paste paste-0.7 mask+0.01: ""(-0.665,2.4) ""(-0.665,2.8) ""(-0.665,0.8) ""(-0.665,1.2) ""(-0.665,1.6) ""(-0.665,2) ""(-0.665,-0.4) ""(-0.665,0) ""(-0.665,0.4) ""(-0.665,-2) ""(-0.665,-1.6) ""(-0.665,-1.2) ""(-0.665,-0.8) ""(-0.665,-2.8) ""(-0.665,-2.4) ""(0.665,2.4) ""(0.665,2.8) ""(0.665,0.8) ""(0.665,1.2) ""(0.665,1.6) ""(0.665,2) ""(0.665,-0.4) ""(0.665,0) ""(0.665,0.4) ""(0.665,-2) ""(0.665,-1.6) ""(0.665,-1.2) ""(0.665,-0.8) ""(0.665,-2.8) ""(0.665,-2.4)
  silkscreen extent -1.28,-3.15 1.28,3.15, body extent -1.16,-3.04 1.16,3.04, height 0.79
FCC_disclaimer [mm]
FP-BAT46GWJ_SOD-123-MFG [mm]
  rrect11% 0.91x1.22 smd paste-1000 mask+0: 1(-1.635,0) 2(1.635,0)
  silkscreen extent -1.83,-1.22 0.8,0.85, body extent -2.29,-1.05 2.29,1.05, height 0.25
FP-EPC2022_LGA30-MFG [mm]
  rrect100% 0.18x0.7 smd paste-1000 mask+0: 1(-2.8,0.665) 2(-2.8,-0.665) 3(-2.4,0.665) 4(-2.4,-0.665) 5(-2,0.665) 6(-2,-0.665) 7(-1.6,0.665) 8(-1.6,-0.665) 9(-1.2,0.665) 10(-1.2,-0.665) 11(-0.8,0.665) 12(-0.8,-0.665) 13(-0.4,0.665) 14(-0.4,-0.665) 15(0,0.665) 16(0,-0.665) 17(0.4,0.665) 18(0.4,-0.665) 19(0.8,0.665) 20(0.8,-0.665) 21(1.2,0.665) 22(1.2,-0.665) 23(1.6,0.665) 24(1.6,-0.665) 25(2,0.665) 26(2,-0.665) 27(2.4,0.665) 28(2.4,-0.665) 30(2.8,-0.665) ""(2.8,0.665)
  silkscreen extent -3.27,-1.16 3.27,1.76, body extent -3.54,-1.67 3.54,1.67, height 0.25
FP-XGL1060-222MEC_SMD2-MFG [mm]
  rrect4% 2.38x8.5 smd paste+0 mask+0: 1(-3.325,0) 2(3.325,0)
  silkscreen extent -5.92,-5.9 5.25,5.9, body extent -5.35,-6 5.35,6, height 0.25
FP-ZG3406-AL_SMT_XFRMR_23MM37_20MM83-MFG [mm] "Recommended Land Pattern"
  round 2.03 smd paste+0 mask+0: 1(-10.41,7.875) 2(-10.41,5.08) 3(-10.41,2.285) 4(-10.41,-2.285) 5(-10.41,-5.08) 6(-10.41,-7.875)
  round 2.79 smd paste+0 mask+0: 7(9.91,-6.35) 8(9.91,-3.175) 10(9.91,3.175) 11(9.91,6.35)
  silkscreen extent -12.36,-10.42 11.69,10.42, body extent -11.69,-10.42 11.69,10.42, height 10.44
IEC_HotSurface_Small [mm]
  silkscreen extent -2.72,-2.36 2.72,2.35
Keystone5010 [mil] "Keystone Multipurpose loops"
  round 87 hole 63: 1(0,0)
  silkscreen extent -70,-70 70,70, body extent -63,-63 63,62, height 319
Keystone5011 [mil] "Keystone Multipurpose loops"
  round 87 hole 63: 1(0,0)
  silkscreen extent -70,-70 70,70, body extent -63,-63 63,62, height 319
KEYSTONE_4820 [mm] "HEX NYLON STANDOFF 6-32, M-F 1\""
  round 0.025 on Mech3: 0(0,0)
  round 3.7 hole 3.6 unplated: MH(0,0)
  silkscreen extent -3.67,-3.67 3.67,3.67, body extent -3.67,-3.17 3.67,3.18, height 25.42
On-Shore_ED120_2DS [mm] "ONSHORE"
  rrect5% 2x2 hole 1.25: 1(-2.54,0)
  round 2 hole 1.25: 2(2.54,0)
  silkscreen extent -5.6,-4 5.12,5, body extent -5.78,-4 5.08,5, height 13
P82xx [mil] "Pulse recommended land pattern"
  rect 60x50 smd: 1(-140,73) 2(-140,0) 3(-140,-73) 4(140,-73) 5(140,0) 6(140,73)
  rect 120x100 smd: 7(0,-103) 8(0,103)
  silkscreen extent -170,-140 170,150, body extent -95,-140 95,140, height 215
PWP0024R-MFG [mm]
  rrect22% 1.5x0.45 smd paste+0 mask+0: 1(-2.9,3.575) 2(-2.9,2.925) 3(-2.9,2.275) 4(-2.9,1.625) 5(-2.9,0.975) 6(-2.9,0.325) 7(-2.9,-0.325) 8(-2.9,-0.975) 9(-2.9,-1.625) 10(-2.9,-2.275) 11(-2.9,-2.925) 12(-2.9,-3.575) 13(2.9,-3.575) 14(2.9,-2.925) 15(2.9,-2.275) 16(2.9,-1.625) 17(2.9,-0.975) 18(2.9,-0.325) 19(2.9,0.325) 20(2.9,0.975) 21(2.9,1.625) 22(2.9,2.275) 23(2.9,2.925) 24(2.9,3.575)
  rrect3% 3.4x7.8 smd paste-1000 mask-1000: 25(0,0)
  silkscreen extent -3.6,-4.3 2.25,4.3, body extent -3.75,-4.2 3.75,4.2, height 0.25
SMA [mm] "Molded Diode, 2-Leads, Body 4.3x2.6mm, IPC Medium Density, based on OnSemi component dimensions and land pattern"
  rect 2x2 smd: 1(-2,0) 2(2,0)
  silkscreen extent -3.66,-1.57 2.79,1.57, body extent -2.6,-1.3 2.6,1.3, height 2.42
WEEE_Minimum [mm] "WEEElie bin"
  silkscreen extent -2.42,-4.38 2.52,2.65
WURTH_61300211121 [mm] "Header, 2.54mm, 2x1, TH"
  rrect50% 1.65x1.65 hole 1.15: 1(-1.27,0)
  round 1.65 hole 1.15: 2(1.27,0)
  body extent -2.54,-1.27 2.54,1.27, height 8.54
WURTH_61300311121 [mm] "Header, 2.54mm, 3x1, TH"
  rrect50% 1.65x1.65 hole 1.15: 1(-2.54,0)
  round 1.65 hole 1.15: 2(0,0) 3(2.54,0)
  body extent -3.81,-1.27 3.81,1.27, height 8.54
WURTH_61300611121 [mm] "Header, 2.54mm, 6x1, TH"
  rrect50% 1.65x1.65 hole 1.15: 1(-6.35,0)
  round 1.65 hole 1.15: 2(-3.81,0) 3(-1.27,0) 4(1.27,0) 5(3.81,0) 6(6.35,0)
  body extent -7.62,-1.27 7.62,1.27, height 8.54

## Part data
C1 C2 C3 C4 C10: library part CMP-0007405-5, "CAP, CERM, 1 uF, 25 V, +/- 10%, X7R, 0603", Cap_Case=0603, Manufacturer=MuRata, Supplier Part Number 1=490-5307-1-ND, TempCo=X7R, Tolerance_%=10%, Value1=Unknown, Value2=25V, ValueDisplayed=1uF
C5: library part CMP-0007402-5, "CAP, CERM, 1000 pF, 25 V, +/- 10%, X7R, 0603", Cap_Case=0603, Manufacturer=MuRata, Supplier Part Number 1=GRM188R71E102KA01D-ND, TempCo=X7R, Tolerance_%=10%, Value1=Unknown, Value2=25V, ValueDisplayed=1000pF
C6: library part CMP-0007138-4, "CAP, CERM, 0.47 uF, 16 V, +/- 10%, X7R, AEC-Q200 Grade 1, 0603", Cap_Case=0603, Manufacturer=MuRata, Supplier Part Number 1=490-4775-1-ND, TempCo=X7R, Tolerance_%=10%, Value1=Unknown, Value2=16V, ValueDisplayed=0.47uF
C7 C8: library part CMP-0007499-4, "CAP, CERM, 2.2 uF, 16 V, +/- 10%, X7R, 0603", Cap_Case=0603, Manufacturer=MuRata, Supplier Part Number 1=81-GRM188Z71C225KE3D, TempCo=X7R, Tolerance_%=10%, Value1=Unknown, Value2=16V, ValueDisplayed=2.2uF
C9: library part CMP-0007450-5, "CAP, CERM, 3300 pF, 50 V, +/- 10%, X7R, 0603", Cap_Case=0603, Manufacturer=MuRata, Supplier Part Number 1=490-1503-1-ND, TempCo=X7R, Tolerance_%=10%, Value1=Unknown, Value2=50V, ValueDisplayed=3300pF
C11: library part CMP-0007129-4, "CAP, CERM, 68 pF, 50 V, +/- 5%, C0G/NP0, AEC-Q200 Grade 1, 0603", Cap_Case=0603, Manufacturer=MuRata, Supplier Part Number 1=490-4961-1-ND, TempCo=C0G/NP0, Tolerance_%=5%, Value1=Unknown, Value2=50V, ValueDisplayed=68pF
C12 C13 C14 C16 C18: library part CMP-0860266-1, "CAP, CERM, 10 µF, 50 V,+/- 10%, X8L, AEC-Q200 Grade 0, 1210", Cap_Case=1210, Manufacturer=MuRata, TempCo=X8L, Tolerance_%=10%, Value2=50V, ValueDisplayed=10µF
C15: library part CMP-0084283-1, "CAP, CERM, 10 pF, 100 V,+/- 5%, C0G/NP0, AEC-Q200 Grade 1, 0603", Cap_Case=0603, Manufacturer=MuRata, TempCo=C0G/NP0, Tolerance_%=5%, Value2=100V, ValueDisplayed=10pF
C17: library part CMP-0008349-2, "CAP, CERM, 0.1 uF, 50 V, +/- 10%, X7R, 0805", Cap_Case=0805, Manufacturer=MuRata, Supplier Part Number 1=490-1666-1-ND, TempCo=X7R, Tolerance_%=10%, Value1=Unknown, Value2=50V, ValueDisplayed=0.1uF
C19: library part CMP-0007443-4, "CAP, CERM, 2200 pF, 50 V, +/- 10%, X7R, 0603", Cap_Case=0603, Manufacturer=MuRata, Supplier Part Number 1=490-1500-1-ND, TempCo=X7R, Tolerance_%=10%, Value1=Unknown, Value2=50V, ValueDisplayed=2200pF
C20 C22 C24 C26: library part CMP-0008137-2, "CAP, CERM, 0.22 uF, 10 V, +/- 10%, X7R, 0805", Cap_Case=0805, Manufacturer=MuRata, Supplier Part Number 1=490-1693-1-ND, TempCo=X7R, Tolerance_%=10%, Value1=Unknown, Value2=10V, ValueDisplayed=0.22uF
C21 C23 C25 C27 C29: library part CMP-0006682-2, "CAP, CERM, 220 pF, 50 V, +/- 10%, X7R, 0402", Cap_Case=0402, Manufacturer=MuRata, Supplier Part Number 1=490-1298-1-ND, TempCo=X7R, Tolerance_%=10%, Value1=Unknown, Value2=50V, ValueDisplayed=220pF
C28 C30 C32 C34: library part CMP-0009088-1, "CAP, CERM, 4.7 uF, 10 V, +/- 10%, X7R, 1210", Cap_Case=1210, Manufacturer=Kemet, Supplier Part Number 1=399-8239-1-ND, TempCo=X7R, Tolerance_%=10%, Value1=Unknown, Value2=10V, ValueDisplayed=4.7uF
C31 C33: library part CMP-0011640-3, "CAP, TA, 100 uF, 10 V, +/- 10%, 0.15 ohm, SMD", Cap_Case=U, Manufacturer=Kemet, Supplier Part Number 1=399-5198-1-ND, Tolerance_%=10%, Value1="0.15 ohm", Value2=10V, ValueDisplayed=100uF
D1 D2: library part CMP-0028597-2, "Diode, Schottky, 100 V, 1 A, SMA", Manufacturer="Micro Commercial Components", Value1=1A, Value2=0.85V
D3: library part CMP-0090343-1, "Diode Schottky 100V 250mA (DC) Surface Mount SOD-123", Digikey Part Number=1727-7326-1-ND, Forward Current=250mA, Manufacturer=Nexperia, Max Surge Forward Current=2.5A, Mouser Part Number=841-BAT46GWJ, Operating Temperature Range="to +150°C", Peak Reverse Current=2uA, ValueDisplayed=39pF
H1 H2 H3 H4: library part CMP-0003652-1, Manufacturer=Keystone, Supplier Part Number 1=36-4820-ND
J1: library part CMP-0054801-2, "Header, 2.54 mm, 6x1, Gold, TH", Color=Black, Manufacturer="Wurth Elektronik", Supplier Part Number 1=732-5319-ND
J2 J5: library part CMP-0054796-4, "Header, 2.54 mm, 3x1, Gold, TH", Manufacturer="Wurth Elektronik", Supplier Part Number 1=732-5316-ND
J3: library part CMP-0054794-2, "Header, 2.54 mm, 2x1, Gold, TH", Color=Black, Manufacturer="Wurth Elektronik", Supplier Part Number 1=732-5315-ND
J4 J6: library part CMP-0074910-1, "Terminal Block, 5.08 mm, 2x1, Brass, TH", Color=Blue, Current_A=15A, Manufacturer="On-Shore Technology", Supplier Part Number 1=ED1609-ND, Voltage_V=300V
L1: library part CMP-0122785-1, "2.2 µH Shielded Molded Inductor 25.3 A 4.3mOhm Max Nonstandard", Digikey Part Number=2457-XGL1060-222MEC-ND, Manufacturer=Coilcraft, Operating Temperature Range=to, Self Resonant Frequency=25MHz, Test Frequency=1MHz, Tolerance_%=20%
Logo1: library part CMP-0074837-2, "IEC 61010-1 Hot Surface Warning", Manufacturer="Texas Instruments"
Logo2: library part CMP-0074847-1, "FCC_disclaimer"
Logo3: library part CMP-0074769-1
Q1: library part CMP-0047741-1, "MOSFET N-Channel 100 V 90A (Ta) Surface Mount Die", Digikey Part Number=917-1133-1-ND, Drain To Source Breakdown Voltage=100V, Input Capacitace At Vds="1400pF @ 50V", Manufacturer=EPC, Operating Temperature Range="-40°C to +150°C", Pulse Drain Current=390A, Typ Forward Diode Voltage=1.8V
Q2 Q3: library part CMP-0000717-1, "MOSFET, N-CH, 40 V, 90 A, 6.05x2.3mm", Alternate Manufacturer=None, Manufacturer=EPC, Supplier Part Number 1=917-1106-1-ND, Value2="18 nC"
R1 R3 R9 R17 R22 R24 R28: library part CMP-0021998-4, "RES, 10.0 k, 1%, 0.1 W, AEC-Q200 Grade 0, 0603", Manufacturer=Vishay-Dale, Power_W=100mW, Supplier Part Number 1=541-10.0KHCT-ND, TempCo="100 ppm/C", Tolerance_%=1%, Value2=0.1W, Value_Code=10k0, ValueDisplayed=10.0k
R2: library part CMP-0022373-4, "RES, 3.16 k, 1%, 0.1 W, AEC-Q200 Grade 0, 0603", Manufacturer=Vishay-Dale, Power_W=100mW, Supplier Part Number 1=541-3.16KHCT-ND, TempCo="100 ppm/C", Tolerance_%=1%, Value2=0.1W, Value_Code=3k16, ValueDisplayed=3.16k
R4 R10: library part CMP-0022507-4, "RES, 59.0 k, 1%, 0.1 W, AEC-Q200 Grade 0, 0603", Manufacturer=Vishay-Dale, Power_W=100mW, Supplier Part Number 1=541-59.0KHCT-ND, TempCo="100 ppm/C", Tolerance_%=1%, Value2=0.1W, Value_Code=59k0, ValueDisplayed=59.0k
R5 R6 R7: library part CMP-0022170-4, "RES, 1.00, 1%, 0.1 W, AEC-Q200 Grade 0, 0603", Manufacturer=Vishay-Dale, Power_W=100mW, Supplier Part Number 1=52K8059, TempCo="100 ppm/C", Tolerance_%=1%, Value2=0.1W, Value_Code=1R00, ValueDisplayed=1.00
R8: library part CMP-0023404-3, "RES, 10.0 k, 0.1%, 0.1 W, 0603", Manufacturer="Susumu Co Ltd", Power_W=100mW, Supplier Part Number 1=RG16P10.0KBCT-ND, TempCo="25 ppm/C", Tolerance_%=0.1%, Value2=0.1W, Value_Code=10k0, ValueDisplayed=10.0k
R11 R13: library part CMP-0022445-4, "RES, 499 k, 1%, 0.1 W, AEC-Q200 Grade 0, 0603", Manufacturer=Vishay-Dale, Power_W=100mW, Supplier Part Number 1=541-499KHCT-ND, TempCo="100 ppm/C", Tolerance_%=1%, Value2=0.1W, Value_Code=499k
R12: library part CMP-0022420-4, "RES, 432 k, 1%, 0.1 W, AEC-Q200 Grade 0, 0603", Manufacturer=Vishay-Dale, Power_W=100mW, Supplier Part Number 1=541-432KHCT-ND, TempCo="100 ppm/C", Tolerance_%=1%, Value2=0.1W, Value_Code=432k
R14: library part CMP-0022090-4, "RES, 17.8 k, 1%, 0.1 W, AEC-Q200 Grade 0, 0603", Manufacturer=Vishay-Dale, Power_W=100mW, Supplier Part Number 1=541-17.8KHCT-ND, TempCo="100 ppm/C", Tolerance_%=1%, Value2=0.1W, Value_Code=17k8, ValueDisplayed=17.8k
R15 R16: library part CMP-0022195-4, "RES, 1.80, 1%, 0.1 W, AEC-Q200 Grade 0, 0603", Manufacturer=Vishay-Dale, Power_W=100mW, Supplier Part Number 1=541-1.80HHCT-ND, TempCo="100 ppm/C", Tolerance_%=1%, Value2=0.1W, Value_Code=1R80, ValueDisplayed=1.80
R18 R19: library part CMP-0022124-4, "RES, 1.43 k, 1%, 0.1 W, AEC-Q200 Grade 0, 0603", Manufacturer=Vishay-Dale, Power_W=100mW, Supplier Part Number 1=541-1.43KHCT-ND, TempCo="100 ppm/C", Tolerance_%=1%, Value2=0.1W, Value_Code=1k43, ValueDisplayed=1.43k
R20 R21 R26 R27: library part CMP-0022317-4, "RES, 2.87, 1%, 0.1 W, AEC-Q200 Grade 0, 0603", Manufacturer=Vishay-Dale, Power_W=100mW, Supplier Part Number 1=541-2.87HHCT-ND, TempCo="100 ppm/C", Tolerance_%=1%, Value2=0.1W, Value_Code=2R87, ValueDisplayed=2.87
R23: library part CMP-0015326-3, "RES, 0.1, 5%, 0.25 W, AEC-Q200 Grade 0, 1210", Manufacturer=Panasonic, Power_W=250mW, Supplier Part Number 1=P.10SCT-ND, TempCo="200 ppm/C", Tolerance_%=5%, Value2=0.25W, Value_Code=R100, ValueDisplayed=0.1
R25: library part CMP-0022003-4, "RES, 10.0, 1%, 0.1 W, AEC-Q200 Grade 0, 0603", Manufacturer=Vishay-Dale, Power_W=100mW, Supplier Part Number 1=541-10.0HCT-ND, TempCo="100 ppm/C", Tolerance_%=1%, Value2=0.1W, Value_Code=10R0, ValueDisplayed=10.0
R29: library part CMP-0015024-3, "RES, 10.0, 1%, 1 W, AEC-Q200 Grade 0, 1218", Manufacturer=Vishay-Dale, Power_W=1W, Supplier Part Number 1=RCL10.0ACT-ND, TempCo="100 ppm/C", Tolerance_%=1%, Value_Code=10R0, ValueDisplayed=10.0
R30: library part CMP-0021145-3, "RES, 2.21, 1%, 0.125 W, AEC-Q200 Grade 0, 0805", Manufacturer=Vishay-Dale, Power_W=125mW, Supplier Part Number 1=541-2.21CCCT-ND, TempCo="100 ppm/C", Tolerance_%=1%, Value2=0.125W, Value_Code=2R21, ValueDisplayed=2.21
T1: library part CMP-0125914-1, "TRANSFORMER", Manufacturer=Coilcraft, Operating Temperature Range=to, Voltage_Isolation_Vrms=1.5kV
T2: library part CMP-0030382-2, "SMT Current Sense Tranformer", Manufacturer="Pulse Engineering"
TP1 TP3: library part CMP-0055147-2, "Test Point, Multipurpose, Red, TH", Color=Red, Manufacturer="Keystone Electronics", Supplier Part Number 1=36-5010-ND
